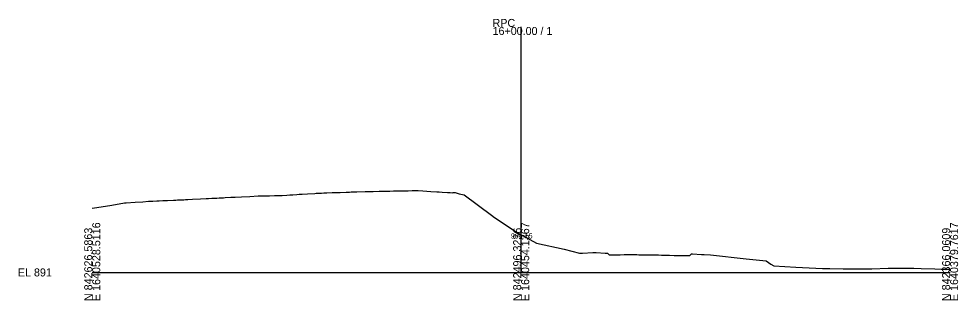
# Model space of a CAD drawing. Extents: x -26 to 1640245, y -10 to 842531.
# Drawn here: x 1274.3 to 1602.8, y 1990.3 to 2088.5 of the extents above; entities that cross this region are included whole.
import ezdxf

# ---------------------------------------------------------------- set-up
doc = ezdxf.new("R2010")
doc.units = 0
for name, color, linetype in [('Exist Cross Section Cell', 7, 'Continuous'), ('Exist XS Center Line Elevation Label', 7, 'Continuous'), ('Exist XS Ground Line', 7, 'Continuous')]:
    doc.layers.add(name, color=color, linetype=linetype)

msp = doc.modelspace()

# ---------------------------------------------------------------- linework, layer by layer
at = {"layer": 'Exist Cross Section Cell'}
for p, q in [((1450, 2000), (1450, 2085.71)), ((1300, 2000), (1450, 2000)), ((1450, 2000), (1600, 2000))]:
    msp.add_line(p, q, dxfattribs=at)
at = {"layer": 'Exist XS Ground Line'}
msp.add_lwpolyline([(1300, 2022.46), (1300.82, 2022.57), (1304.63, 2023.19), (1306.79, 2023.54), (1311.29, 2024.27), (1311.9, 2024.34), (1314.96, 2024.51), (1317.66, 2024.7), (1319.69, 2024.84), (1320.52, 2024.88), (1321.13, 2024.9), (1322.63, 2024.97), (1323.42, 2025.01), (1324.73, 2025.07), (1326.3, 2025.15), (1328.38, 2025.23), (1329.18, 2025.26), (1329.77, 2025.29), (1332.05, 2025.4), (1332.59, 2025.43), (1333.45, 2025.47), (1335.09, 2025.55), (1337.81, 2025.69), (1339.86, 2025.78), (1340.39, 2025.8), (1340.69, 2025.82), (1341.8, 2025.87), (1343.57, 2025.96), (1344.33, 2026), (1345.25, 2026.05), (1345.86, 2026.09), (1346.45, 2026.12), (1348.51, 2026.23), (1349.55, 2026.29), (1349.94, 2026.31), (1352.21, 2026.43), (1355.08, 2026.56), (1358.07, 2026.7), (1360.02, 2026.74), (1360.84, 2026.76), (1361.93, 2026.79), (1363.72, 2026.84), (1365.07, 2026.87), (1366.46, 2026.91), (1368.03, 2026.99), (1369.07, 2027.05), (1369.46, 2027.06), (1370.11, 2027.11), (1371.54, 2027.22), (1372.36, 2027.27), (1373.37, 2027.33), (1375.32, 2027.45), (1377.85, 2027.61), (1378.25, 2027.63), (1380.19, 2027.71), (1380.99, 2027.74), (1382.06, 2027.78), (1383.87, 2027.85), (1385.23, 2027.9), (1386.75, 2027.95), (1388.77, 2028.03), (1389.91, 2028.07), (1390.56, 2028.09), (1391.41, 2028.11), (1392.51, 2028.14), (1395.39, 2028.23), (1397.19, 2028.27), (1398.27, 2028.29), (1400.36, 2028.35), (1401.15, 2028.37), (1402, 2028.38), (1402.96, 2028.39), (1404.02, 2028.4), (1405.4, 2028.43), (1406.9, 2028.46), (1408.9, 2028.5), (1409.78, 2028.52), (1410.44, 2028.53), (1411.85, 2028.55), (1412.66, 2028.57), (1414.01, 2028.55), (1415.61, 2028.51), (1418.42, 2028.28), (1420.53, 2028.15), (1421.3, 2028.11), (1422.32, 2028.05), (1424.18, 2027.95), (1424.65, 2027.92), (1425.13, 2027.88), (1425.87, 2027.75), (1426.27, 2027.86), (1426.93, 2027.96), (1428.37, 2027.46), (1430.06, 2027.07), (1439.67, 2019.95), (1440.7, 2019.2), (1441.58, 2018.64), (1448.03, 2014.26), (1450, 2013.15), (1451.71, 2012.19), (1455.36, 2010.22), (1465.06, 2008.13), (1470.44, 2006.7), (1471.45, 2006.71), (1475.04, 2006.95), (1475.38, 2006.97), (1475.83, 2006.94), (1476.2, 2006.92), (1479.32, 2006.76), (1480.24, 2006.71), (1480.77, 2006.19), (1482.63, 2006.19), (1484.63, 2006.19), (1486.07, 2006.2), (1487.51, 2006.2), (1489.42, 2006.2), (1490.39, 2006.2), (1491.12, 2006.19), (1493.27, 2006.16), (1494.44, 2006.14), (1494.88, 2006.14), (1496.16, 2006.11), (1497.98, 2006.09), (1499.02, 2006.07), (1499.82, 2006.05), (1501.2, 2006.02), (1501.9, 2006), (1503.48, 2005.96), (1504.78, 2005.94), (1505.8, 2005.91), (1507.22, 2005.86), (1508.19, 2005.88), (1509.03, 2005.88), (1509.59, 2006.48), (1509.95, 2006.46), (1513.02, 2006.31), (1514.04, 2006.25), (1516.19, 2006.15), (1528.68, 2004.73), (1535.67, 2004.02), (1537.36, 2002.93), (1538.39, 2002.3), (1546.1, 2001.87), (1555.35, 2001.36), (1557.98, 2001.32), (1562.6, 2001.26), (1565.31, 2001.31), (1566.87, 2001.3), (1572.65, 2001.23), (1578.38, 2001.46), (1579.98, 2001.49), (1582.77, 2001.45), (1587.31, 2001.45), (1589.9, 2001.32), (1594.64, 2001.29), (1596.85, 2001.19), (1600, 2001.09)], dxfattribs=at)

# ---------------------------------------------------------------- texts
at = {"layer": 'Exist Cross Section Cell'}
for s, p in [('RPC', (1440, 2085.71)), ('16+00.00 / 1', (1440, 2082.91)), ('EL 891', (1274, 1998.6))]:
    msp.add_text(s, height=2.8, dxfattribs=at).set_placement(p)
for s, p in [('E 1640528.5116', (1302.8, 1990)), ('E 1640454.1367', (1452.8, 1990)), ('E 1640379.7617', (1602.8, 1990)), ('N 842626.5863', (1300, 1990)), ('N 842496.3236', (1450, 1990)), ('N 842366.0609', (1600, 1990))]:
    msp.add_text(s, height=2.8, rotation=90, dxfattribs=at).set_placement(p)
at = {"layer": 'Exist XS Center Line Elevation Label'}
msp.add_text('904.15', height=1.8, dxfattribs=at).set_placement((1446.38, 2011.85))

doc.saveas('drawing.dxf')
